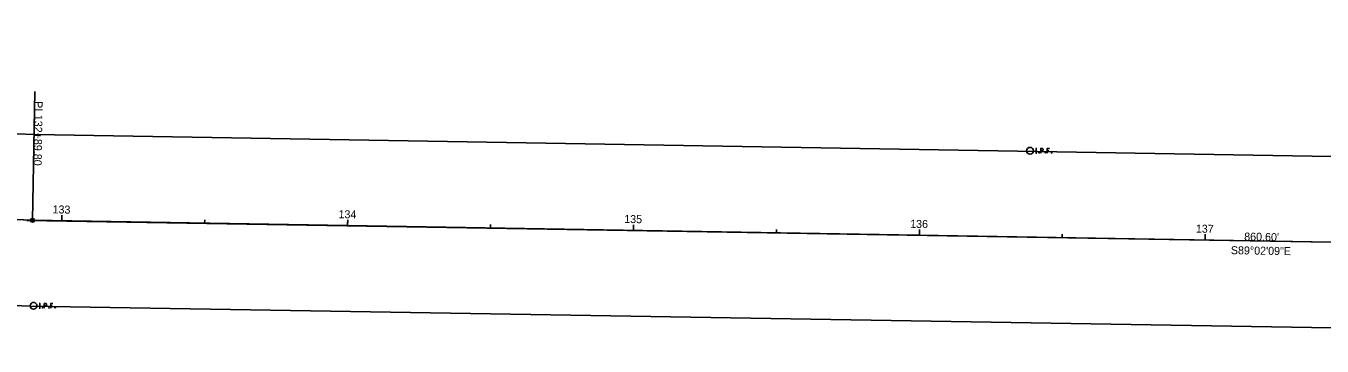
# Model space of a CAD drawing. Extents: x 2003596 to 2006933, y 570827 to 573780.
# Drawn here: x 2006021.3 to 2006474.6, y 572553.3 to 572665.2 of the extents above; entities that cross this region are included whole.
import ezdxf

# ---------------------------------------------------------------- set-up
doc = ezdxf.new("R2010")
doc.units = 0
for name, color, linetype in [('DT_X_Spot_Elev', 7, 'Continuous'), ('GE_X_Alignment', 7, 'Continuous'), ('GE_X_Alignment_1000_Bearings', 7, 'Continuous'), ('GE_X_Alignment_1000_Cardinal_Points', 7, 'Continuous'), ('GE_X_Alignment_1000_Distances', 7, 'Continuous'), ('GE_X_Alignment_1000_Stations', 7, 'Continuous'), ('GE_X_Alignment_100_Bearings', 7, 'Continuous'), ('GE_X_Alignment_100_Cardinal_Points', 7, 'Continuous'), ('GE_X_Alignment_100_Distances', 7, 'Continuous'), ('GE_X_Alignment_100_Stations', 7, 'Continuous'), ('GE_X_Alignment_500_Bearings', 7, 'Continuous'), ('GE_X_Alignment_500_Cardinal_Points', 7, 'Continuous'), ('GE_X_Alignment_500_Distances', 7, 'Continuous'), ('GE_X_Alignment_500_Stations', 7, 'Continuous'), ('RW_X_CL', 7, 'Continuous'), ('RW_X_Esmt_SH', 7, 'Continuous'), ('SC_Scratch10', 7, 'Continuous'), ('SC_Scratch9', 7, 'Continuous'), ('SV_X_Mon_Cells_Found', 7, 'Continuous'), ('SV_X_Random_Point', 7, 'Continuous')]:
    doc.layers.add(name, color=color, linetype=linetype)

msp = doc.modelspace()

# ---------------------------------------------------------------- linework, layer by layer
at = {"layer": 'DT_X_Spot_Elev'}
for p, q in [((2006023.62, 572597.25), (2005654.09, 572611.43)), ((2006884.1, 572582.77), (2006023.62, 572597.25))]:
    msp.add_line(p, q, dxfattribs=at)
at = {"layer": 'GE_X_Alignment'}
for p, q in [((2005031.48, 572635.32), (2006023.62, 572597.25)), ((2006023.62, 572597.25), (2006884.1, 572582.77))]:
    msp.add_line(p, q, dxfattribs=at)
at = {"layer": 'GE_X_Alignment_1000_Cardinal_Points'}
msp.add_line((2006023.62, 572597.25), (2006024.38, 572642.24), dxfattribs=at)
msp.add_circle((2006023.62, 572597.25), 0.6, dxfattribs=at)
at = {"layer": 'GE_X_Alignment_1000_Stations'}
msp.add_line((2006233.79, 572593.71), (2006233.81, 572594.91), dxfattribs=at)
at = {"layer": 'GE_X_Alignment_100_Cardinal_Points'}
msp.add_line((2006023.62, 572597.25), (2006024.38, 572642.24), dxfattribs=at)
msp.add_circle((2006023.62, 572597.25), 0.6, dxfattribs=at)
at = {"layer": 'GE_X_Alignment_100_Stations'}
for p, q in [((2006033.82, 572597.08), (2006033.85, 572599.08)), ((2006083.81, 572596.24), (2006083.83, 572597.44)), ((2006133.81, 572595.4), (2006133.84, 572597.4)), ((2006183.8, 572594.55), (2006183.82, 572595.75)), ((2006233.79, 572593.71), (2006233.82, 572595.71)), ((2006283.78, 572592.87), (2006283.8, 572594.07)), ((2006333.78, 572592.03), (2006333.81, 572594.03)), ((2006383.77, 572591.19), (2006383.79, 572592.39)), ((2006433.76, 572590.35), (2006433.8, 572592.35))]:
    msp.add_line(p, q, dxfattribs=at)
at = {"layer": 'GE_X_Alignment_500_Cardinal_Points'}
msp.add_line((2006023.62, 572597.25), (2006024.38, 572642.24), dxfattribs=at)
msp.add_circle((2006023.62, 572597.25), 0.6, dxfattribs=at)
at = {"layer": 'GE_X_Alignment_500_Stations'}
for p, q in [((2006033.82, 572597.08), (2006033.84, 572598.28)), ((2006133.81, 572595.4), (2006133.83, 572596.6)), ((2006233.79, 572593.71), (2006233.82, 572595.71)), ((2006333.78, 572592.03), (2006333.8, 572593.23)), ((2006433.76, 572590.35), (2006433.78, 572591.55))]:
    msp.add_line(p, q, dxfattribs=at)
at = {"layer": 'RW_X_CL'}
for p, q in [((2006023.62, 572597.25), (2005031.48, 572635.32)), ((2006884.1, 572582.77), (2006023.62, 572597.25))]:
    msp.add_line(p, q, dxfattribs=at)
at = {"layer": 'RW_X_Esmt_SH'}
for p, q in [((2005034.78, 572665.22), (2006024.45, 572627.24)), ((2006024.45, 572627.24), (2006853.47, 572613.29)), ((2005028.18, 572605.42), (2006022.8, 572567.26)), ((2006022.8, 572567.26), (2006854.42, 572553.27))]:
    msp.add_line(p, q, dxfattribs=at)
at = {"layer": 'SC_Scratch10'}
msp.add_line((2006023.71, 572597.25), (2005465.42, 572618.88), dxfattribs=at)
at = {"layer": 'SC_Scratch9'}
for p, q in [((2006371.52, 572591.34), (2006021.57, 572597.19)), ((2006884.1, 572582.77), (2006371.52, 572591.34))]:
    msp.add_line(p, q, dxfattribs=at)
at = {"layer": 'SV_X_Mon_Cells_Found'}
for points in [[(2006374.5, 572622.36), (2006374.86, 572622.36)], [(2006374.68, 572620.76), (2006374.68, 572622.36)], [(2006376.25, 572620.76), (2006376.25, 572622.36), (2006376.77, 572622.36), (2006376.83, 572622.35), (2006376.91, 572622.32), (2006376.94, 572622.3), (2006376.97, 572622.27), (2006377.02, 572622.21), (2006377.05, 572622.15), (2006377.07, 572622.05), (2006377.07, 572621.89), (2006377.06, 572621.84), (2006377.04, 572621.77), (2006377, 572621.68), (2006376.95, 572621.64), (2006376.92, 572621.62), (2006376.86, 572621.59), (2006376.77, 572621.58), (2006376.25, 572621.58)], [(2006379.26, 572622.36), (2006378.49, 572622.36), (2006378.49, 572620.76)], [(2006378.49, 572621.58), (2006379.03, 572621.58)], [(2006374.5, 572620.76), (2006374.86, 572620.76)], [(2006375.64, 572620.97), (2006375.69, 572620.97), (2006375.73, 572620.95), (2006375.76, 572620.9), (2006375.76, 572620.84), (2006375.73, 572620.79), (2006375.69, 572620.76), (2006375.64, 572620.76), (2006375.61, 572620.79), (2006375.57, 572620.84), (2006375.57, 572620.9), (2006375.61, 572620.95), (2006375.64, 572620.97)], [(2006377.89, 572620.97), (2006377.94, 572620.97), (2006377.98, 572620.95), (2006378.01, 572620.9), (2006378.01, 572620.84), (2006377.98, 572620.79), (2006377.94, 572620.76), (2006377.89, 572620.76), (2006377.86, 572620.79), (2006377.82, 572620.84), (2006377.82, 572620.9), (2006377.86, 572620.95), (2006377.89, 572620.97)], [(2006380.04, 572620.97), (2006380.09, 572620.97), (2006380.13, 572620.95), (2006380.16, 572620.9), (2006380.16, 572620.84), (2006380.13, 572620.79), (2006380.09, 572620.76), (2006380.04, 572620.76), (2006380, 572620.79), (2006379.97, 572620.84), (2006379.97, 572620.9), (2006380, 572620.95), (2006380.04, 572620.97)], [(2006025.97, 572568.15), (2006026.33, 572568.15)], [(2006026.15, 572566.55), (2006026.15, 572568.15)], [(2006027.72, 572566.55), (2006027.72, 572568.15), (2006028.24, 572568.15), (2006028.3, 572568.14), (2006028.38, 572568.11), (2006028.41, 572568.09), (2006028.44, 572568.06), (2006028.49, 572568), (2006028.52, 572567.94), (2006028.54, 572567.84), (2006028.54, 572567.68), (2006028.53, 572567.63), (2006028.51, 572567.56), (2006028.47, 572567.47), (2006028.42, 572567.43), (2006028.39, 572567.41), (2006028.33, 572567.38), (2006028.24, 572567.37), (2006027.72, 572567.37)], [(2006030.72, 572568.15), (2006029.96, 572568.15), (2006029.96, 572566.55)], [(2006029.96, 572567.37), (2006030.5, 572567.37)], [(2006025.97, 572566.55), (2006026.33, 572566.55)], [(2006027.11, 572566.76), (2006027.16, 572566.76), (2006027.2, 572566.74), (2006027.23, 572566.69), (2006027.23, 572566.63), (2006027.2, 572566.58), (2006027.16, 572566.55), (2006027.11, 572566.55), (2006027.08, 572566.58), (2006027.04, 572566.63), (2006027.04, 572566.69), (2006027.08, 572566.74), (2006027.11, 572566.76)], [(2006029.36, 572566.76), (2006029.41, 572566.76), (2006029.45, 572566.74), (2006029.48, 572566.69), (2006029.48, 572566.63), (2006029.45, 572566.58), (2006029.41, 572566.55), (2006029.36, 572566.55), (2006029.32, 572566.58), (2006029.29, 572566.63), (2006029.29, 572566.69), (2006029.32, 572566.74), (2006029.36, 572566.76)], [(2006031.51, 572566.76), (2006031.56, 572566.76), (2006031.6, 572566.74), (2006031.63, 572566.69), (2006031.63, 572566.63), (2006031.6, 572566.58), (2006031.56, 572566.55), (2006031.51, 572566.55), (2006031.47, 572566.58), (2006031.44, 572566.63), (2006031.44, 572566.69), (2006031.47, 572566.74), (2006031.51, 572566.76)]]:
    msp.add_lwpolyline(points, dxfattribs=at)
for centre in [(2006372.49, 572621.56), (2006023.96, 572567.35)]:
    msp.add_circle(centre, 1.2, dxfattribs=at)
at = {"layer": 'SV_X_Random_Point'}
for p, q in [((2006022.96, 572596.58), (2006024.29, 572597.92)), ((2006022.96, 572597.92), (2006024.29, 572596.58))]:
    msp.add_line(p, q, dxfattribs=at)

# ---------------------------------------------------------------- texts
at = {"layer": 'GE_X_Alignment_1000_Bearings'}
msp.add_text('S89°02\'09"E', height=2.8, rotation=359.0359, dxfattribs=at).set_placement((2006442.71, 572585.4))
at = {"layer": 'GE_X_Alignment_1000_Cardinal_Points'}
for s, p in [('PI', (2006024.37, 572638.95)), ('132+89.80', (2006024.29, 572634.17))]:
    msp.add_text(s, height=2.8, rotation=269.0359, dxfattribs=at).set_placement(p)
at = {"layer": 'GE_X_Alignment_1000_Distances'}
msp.add_text("860.60'", height=2.8, rotation=359.0359, dxfattribs=at).set_placement((2006447.38, 572590.17))
at = {"layer": 'GE_X_Alignment_100_Bearings'}
msp.add_text('S89°02\'09"E', height=2.8, rotation=359.0359, dxfattribs=at).set_placement((2006442.71, 572585.4))
at = {"layer": 'GE_X_Alignment_100_Cardinal_Points'}
for s, p in [('PI', (2006024.37, 572638.95)), ('132+89.80', (2006024.29, 572634.17))]:
    msp.add_text(s, height=2.8, rotation=269.0359, dxfattribs=at).set_placement(p)
at = {"layer": 'GE_X_Alignment_100_Distances'}
msp.add_text("860.60'", height=2.8, rotation=359.0359, dxfattribs=at).set_placement((2006447.38, 572590.17))
at = {"layer": 'GE_X_Alignment_100_Stations'}
for s, p in [('133', (2006030.6, 572599.68)), ('134', (2006130.61, 572598)), ('135', (2006230.54, 572596.32)), ('136', (2006330.54, 572594.63)), ('137', (2006430.47, 572592.95))]:
    msp.add_text(s, height=2.8, rotation=359.0359, dxfattribs=at).set_placement(p)
at = {"layer": 'GE_X_Alignment_500_Bearings'}
msp.add_text('S89°02\'09"E', height=2.8, rotation=359.0359, dxfattribs=at).set_placement((2006442.71, 572585.4))
at = {"layer": 'GE_X_Alignment_500_Cardinal_Points'}
for s, p in [('PI', (2006024.37, 572638.95)), ('132+89.80', (2006024.29, 572634.17))]:
    msp.add_text(s, height=2.8, rotation=269.0359, dxfattribs=at).set_placement(p)
at = {"layer": 'GE_X_Alignment_500_Distances'}
msp.add_text("860.60'", height=2.8, rotation=359.0359, dxfattribs=at).set_placement((2006447.38, 572590.17))
at = {"layer": 'GE_X_Alignment_500_Stations'}
msp.add_text('135', height=2.8, rotation=359.0359, dxfattribs=at).set_placement((2006230.54, 572596.32))

doc.saveas('drawing.dxf')
